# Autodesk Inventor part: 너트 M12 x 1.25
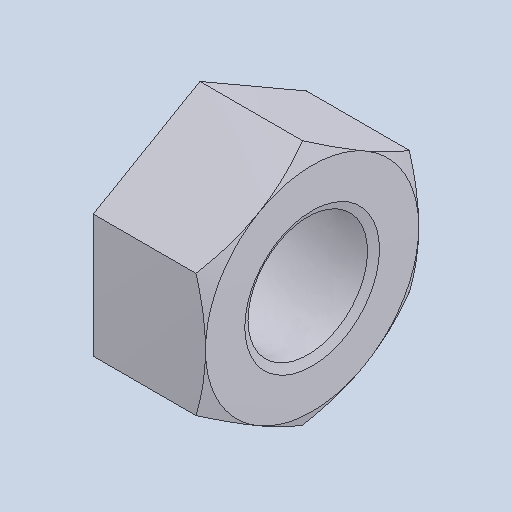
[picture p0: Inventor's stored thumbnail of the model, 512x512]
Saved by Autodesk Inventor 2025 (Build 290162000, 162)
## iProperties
Created: 2024-08
Part Number: 너트 M12 x 1.25
Material: 스테인리스강
Description: 6각 너트
Document SubType Name: Modeling
Designer: SAMSUNG
Density: 8.08 g/cm^3
Appearance: 기본값
Author: jhkim
Sending System: Autodesk Inventor 2025
Preprocessor: ST-DEVELOPER v20
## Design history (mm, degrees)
feature "Solid1"
node "솔리드1"
